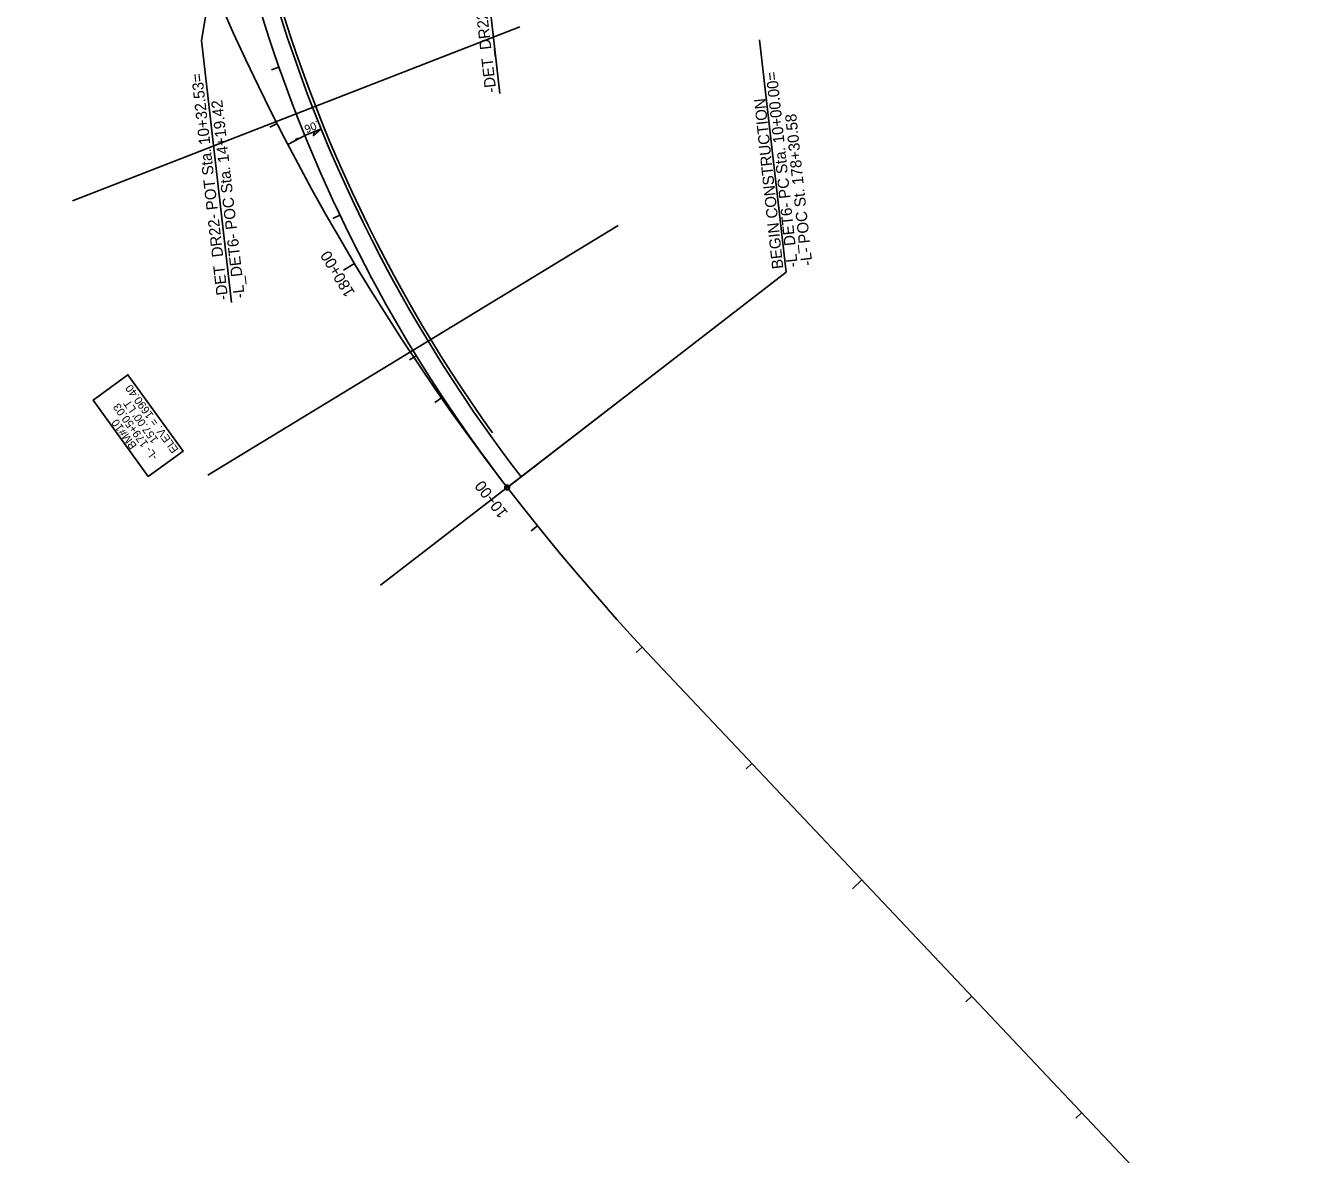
# Model space of a CAD drawing. Extents: x 473658 to 481584, y 489119 to 506230.
# Drawn here: x 474521 to 475318, y 502974 to 503679 of the extents above; entities that cross this region are included whole.
import ezdxf

# ---------------------------------------------------------------- set-up
doc = ezdxf.new("R2010")
doc.units = 0
for name, color, linetype in [('Default', 7, 'Continuous'), ('Prop EOT', 7, 'Continuous'), ('Prop Grid Mask', 7, 'Continuous'), ('Prop Horizontal Alignment', 7, 'Continuous'), ('Prop Horizontal Alignment Station Label', 7, 'Continuous'), ('Prop Horizontal Alignment Tick Label', 7, 'Continuous'), ('Prop Horizontal Alignment Tick Large', 7, 'Continuous'), ('Prop Horizontal Alignment Tick Small', 7, 'Continuous'), ('Prop Paved Shoulder', 7, 'Continuous'), ('Prop Superelevation  Arrow CELL', 7, 'Continuous'), ('Prop Superelevation Label', 7, 'Continuous'), ('Scratch_Level_6', 7, 'Continuous'), ('Scratch_Level_9', 7, 'Continuous')]:
    doc.layers.add(name, color=color, linetype=linetype)

msp = doc.modelspace()

# ---------------------------------------------------------------- linework, layer by layer
at = {"layer": 'Prop EOT'}
msp.add_arc((475566.35, 503964.84), 929, 193.01816, 217.6526, dxfattribs=at)
at = {"layer": 'Prop Grid Mask'}
msp.add_lwpolyline([(474597.88, 503397.58), (474563.37, 503445.24), (474585.18, 503461.03), (474619.68, 503413.37)], close=True, dxfattribs=at)
at = {"layer": 'Prop Horizontal Alignment'}
msp.add_line((475317.78, 502855.51), (474915.81, 503280.98), dxfattribs=at)
for centre, radius, start, end in [((475966.17, 504273.33), 1445, 176.96875, 223.37358), ((475566.35, 503964.84), 940, 182.02426, 217.6526)]:
    msp.add_arc(centre, radius, start, end, dxfattribs=at)
at = {"layer": 'Prop Horizontal Alignment Station Label'}
for p, q in [((474817.62, 503636.69), (474801.03, 503781.12)), ((474631.17, 503669.72), (474647.19, 503768)), ((474631.17, 503669.72), (474649.97, 503506.1)), ((474996.46, 503525.14), (474979.72, 503670.29)), ((474823.31, 503391.54), (474996.46, 503525.14))]:
    msp.add_line(p, q, dxfattribs=at)
msp.add_circle((474822.12, 503390.62), 1.5, dxfattribs=at)
msp.add_circle((474822.12, 503390.62), 1.5, dxfattribs=at)
msp.add_circle((474822.12, 503390.62), 1.5, dxfattribs=at)
at = {"layer": 'Prop Horizontal Alignment Tick Large'}
for p, q in [((474726.72, 503530.51), (474719.86, 503526.4)), ((474822.12, 503390.62), (474815.79, 503385.74)), ((475043.75, 503145.56), (475037.94, 503140.06))]:
    msp.add_line(p, q, dxfattribs=at)
at = {"layer": 'Prop Horizontal Alignment Tick Small'}
for p, q in [((474679.54, 503653.13), (474674.82, 503651.47)), ((474678.32, 503617.99), (474673.86, 503615.73)), ((474717.65, 503560.73), (474713.13, 503558.58)), ((474765.36, 503472.89), (474761.1, 503470.28)), ((474781.05, 503446.58), (474776.95, 503443.72)), ((474841.06, 503366.61), (474837.16, 503363.47)), ((474906.45, 503290.98), (474902.78, 503287.58)), ((474975.08, 503218.25), (474971.44, 503214.81)), ((475112.43, 503072.87), (475108.79, 503069.43)), ((475181.1, 503000.18), (475177.47, 502996.75))]:
    msp.add_line(p, q, dxfattribs=at)
at = {"layer": 'Prop Paved Shoulder'}
msp.add_arc((475566.35, 503964.84), 927, 192.6457, 215.63836, dxfattribs=at)
at = {"layer": 'Prop Superelevation  Arrow CELL'}
msp.add_lwpolyline([(474705.91, 503614.56), (474701.11, 503610.45), (474701.63, 503612.82)], close=True, dxfattribs=at)
at = {"layer": 'Prop Superelevation Label'}
msp.add_line((474705.91, 503614.56), (474695.73, 503610.42), dxfattribs=at)
at = {"layer": 'Scratch_Level_6'}
for p, q in [((474550.5, 503569.67), (474830.09, 503678.44)), ((474695.73, 503610.42), (474685.09, 503604.86)), ((474689.58, 503607.74), (474691.71, 503608.85)), ((474635.12, 503398.35), (474891.42, 503554.26))]:
    msp.add_line(p, q, dxfattribs=at)
msp.add_lwpolyline([(474691.71, 503608.85), (474691.27, 503608.4), (474691.3, 503608.64)], close=True, dxfattribs=at)
at = {"layer": 'Scratch_Level_9'}
msp.add_line((474742.95, 503329.53), (474901.29, 503451.71), dxfattribs=at)

# ---------------------------------------------------------------- texts
at = {"layer": 'Default'}
for s, p in [('ELEV. = 1690.40', (474616.99, 503414.33)), ('ELEV. = 1690.40', (474616.99, 503414.33)), ('-L- 179+50.03', (474604.04, 503409.86)), ('-L- 179+50.03', (474604.04, 503409.86)), ("157.00' LT", (474604.43, 503420.5)), ("157.00' LT", (474604.43, 503420.5)), ('BM#10', (474590.95, 503416.76)), ('BM#10', (474590.95, 503416.76))]:
    msp.add_text(s, height=5, rotation=125.90742, dxfattribs=at).set_placement(p)
at = {"layer": 'Prop Horizontal Alignment Station Label'}
for s, rotation, p in [('-DET_DR22- PC Sta.  11+87.17', 96.55384, (474815.37, 503637.59)), ('-DET_DR22- POT Sta. 10+32.53=', 96.55384, (474647.83, 503507.97)), ('-L_DET6- PC Sta. 10+00.00=', 96.14289, (475003.77, 503528.45)), ('-L_DET6- POC Sta. 14+19.42', 96.55384, (474658.26, 503509.17)), ('BEGIN CONSTRUCTION', 96.14289, (474994.69, 503527.47)), ('-L- POC St. 178+30.58', 96.14289, (475012.85, 503529.43))]:
    msp.add_text(s, height=7, rotation=rotation, dxfattribs=at).set_placement(p)
at = {"layer": 'Prop Horizontal Alignment Tick Label'}
for s, rotation, p in [('180+00', 120.93497, (474727.19, 503512.22)), ('10+00', 127.6526, (474822.94, 503374.83))]:
    msp.add_text(s, height=7, rotation=rotation, dxfattribs=at).set_placement(p)
at = {"layer": 'Prop Superelevation Label'}
msp.add_text('.06', height=5, rotation=202.1511, dxfattribs=at).set_placement((474703.47, 503619.9))
at = {"layer": 'Scratch_Level_6'}
msp.add_text('.06', height=0.5, rotation=207.5545, dxfattribs=at).set_placement((474691.1, 503609.33))

doc.saveas('drawing.dxf')
